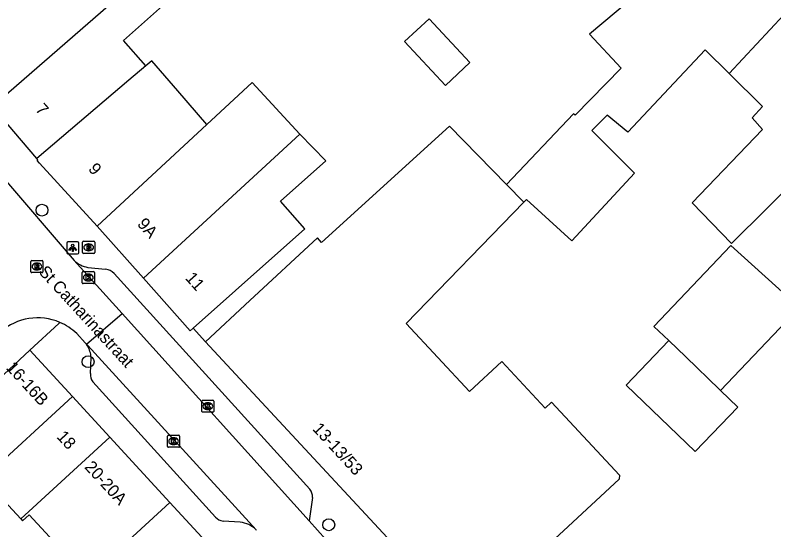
# Model space of a CAD drawing. Extents: x 160664 to 161506, y 382245 to 383288.
# Drawn here: x 160852.6 to 160915.2, y 383074 to 383116.5 of the extents above; entities that cross this region are included whole.
import ezdxf

# ---------------------------------------------------------------- set-up
doc = ezdxf.new("R2010")
doc.units = 0
for name, color, linetype in [('IMGEO_Boom', 7, 'Continuous'), ('IMGEO_Brandkraan', 7, 'Continuous'), ('IMGEO_Kolk', 7, 'Continuous'), ('IMGEO_Lichtpunt', 7, 'Continuous'), ('IMGEO_Openbare_ruimte_label', 7, 'Continuous'), ('IMGEO_Pand', 7, 'Continuous'), ('IMGEO_Pand_nummerreeks', 7, 'Continuous'), ('IMGEO_Rijbaan_lokaal_open', 7, 'Continuous'), ('IMGEO_Rioolput', 7, 'Continuous'), ('IMGEO_Voetpad_open', 7, 'Continuous')]:
    doc.layers.add(name, color=color, linetype=linetype)

msp = doc.modelspace()

# ---------------------------------------------------------------- linework, layer by layer
at = {"layer": 'IMGEO_Boom'}
for centre in [(160854.782, 383100.356), (160858.596, 383087.847), (160878.479, 383074.385)]:
    msp.add_circle(centre, 0.489, dxfattribs=at)
at = {"layer": 'IMGEO_Brandkraan'}
for p, q in [((160858.142, 383096.859), (160858.142, 383097.711)), ((160858.217, 383097.785), (160859.069, 383097.785)), ((160859.143, 383097.711), (160859.143, 383096.859)), ((160858.63, 383097.565), (160858.655, 383097.565)), ((160859.069, 383096.785), (160858.217, 383096.785)), ((160858.653, 383097.005), (160858.628, 383097.005))]:
    msp.add_line(p, q, dxfattribs=at)
for points in [[(160858.142, 383096.859), (160858.142, 383097.711)], [(160858.217, 383097.785), (160859.069, 383097.785)], [(160859.143, 383097.711), (160859.143, 383096.859)], [(160858.49, 383097.485), (160858.49, 383097.085), (160858.703, 383097.085)], [(160858.721, 383097.485), (160858.49, 383097.485)], [(160858.669, 383097.404), (160858.615, 383097.404), (160858.615, 383097.328)], [(160858.615, 383097.328), (160858.668, 383097.328)], [(160858.677, 383097.252), (160858.615, 383097.252), (160858.615, 383097.171)], [(160858.615, 383097.171), (160858.677, 383097.171)], [(160859.069, 383096.785), (160858.217, 383096.785)]]:
    msp.add_lwpolyline(points, dxfattribs=at)
for centre, radius, start, end in [((160858.219, 383097.709), 0.0765, 91.55205, 178.44795), ((160858.219, 383097.709), 0.0765, 91.55205, 178.44795), ((160859.067, 383097.709), 0.0765, 1.55205, 88.44795), ((160859.067, 383097.709), 0.0765, 1.55205, 88.44795), ((160858.67, 383097.366), 0.0379, 267.82845, 90.93552), ((160858.678, 383097.211), 0.0404, 269.87594, 90.50774), ((160858.709, 383097.336), 0.251, 268.66757, 293.53466), ((160858.725, 383097.34), 0.145, 59.4692, 91.53667), ((160858.75, 383097.387), 0.0922, 285.51372, 58.15012), ((160858.755, 383097.195), 0.105, 301.31148, 78.98903), ((160858.219, 383096.861), 0.0765, 181.55205, 268.44795), ((160858.219, 383096.861), 0.0765, 181.55205, 268.44795), ((160859.067, 383096.861), 0.0765, 271.55205, 358.44795), ((160859.067, 383096.861), 0.0765, 271.55205, 358.44795)]:
    msp.add_arc(centre, radius, start, end, dxfattribs=at)
for centre, major_axis, ratio, start_param, end_param in [((160858.629, 383097.285), (-0.387, 0.002), 0.722429, 4.712389, 7.853982), ((160858.654, 383097.285), (-0.39, 0.002), 0.717154, 1.570796, 4.712389)]:
    msp.add_ellipse(centre, major_axis=major_axis, ratio=ratio, start_param=start_param, end_param=end_param, dxfattribs=at)
at = {"layer": 'IMGEO_Kolk'}
for p, q in [((160858.116, 383094.368), (160858.116, 383095.22)), ((160858.191, 383095.294), (160859.043, 383095.294)), ((160859.117, 383095.22), (160859.117, 383094.368)), ((160858.604, 383095.074), (160858.629, 383095.074)), ((160859.043, 383094.294), (160858.191, 383094.294)), ((160858.627, 383094.514), (160858.602, 383094.514)), ((160867.986, 383083.748), (160867.986, 383084.6)), ((160868.061, 383084.674), (160868.913, 383084.674)), ((160868.987, 383084.6), (160868.987, 383083.748)), ((160868.474, 383084.454), (160868.499, 383084.454)), ((160868.913, 383083.674), (160868.061, 383083.674)), ((160868.497, 383083.894), (160868.472, 383083.894)), ((160865.156, 383080.856), (160865.156, 383081.708)), ((160865.231, 383081.782), (160866.083, 383081.782)), ((160865.644, 383081.562), (160865.669, 383081.562)), ((160866.157, 383081.708), (160866.157, 383080.856)), ((160866.083, 383080.782), (160865.231, 383080.782)), ((160865.667, 383081.002), (160865.642, 383081.002))]:
    msp.add_line(p, q, dxfattribs=at)
for points in [[(160858.116, 383094.368), (160858.116, 383095.22)], [(160858.191, 383095.294), (160859.043, 383095.294)], [(160859.117, 383095.22), (160859.117, 383094.368)], [(160858.437, 383094.994), (160858.56, 383094.994), (160858.56, 383094.843), (160858.69, 383094.994), (160858.854, 383094.994), (160858.708, 383094.843), (160858.861, 383094.594), (160858.709, 383094.594), (160858.624, 383094.758), (160858.56, 383094.691), (160858.56, 383094.594), (160858.437, 383094.594), (160858.437, 383094.994)], [(160859.043, 383094.294), (160858.191, 383094.294)], [(160867.986, 383083.748), (160867.986, 383084.6)], [(160868.061, 383084.674), (160868.913, 383084.674)], [(160868.987, 383084.6), (160868.987, 383083.748)], [(160868.307, 383084.374), (160868.43, 383084.374), (160868.43, 383084.223), (160868.56, 383084.374), (160868.724, 383084.374), (160868.578, 383084.223), (160868.731, 383083.974), (160868.579, 383083.974), (160868.494, 383084.138), (160868.43, 383084.071), (160868.43, 383083.974), (160868.307, 383083.974), (160868.307, 383084.374)], [(160868.913, 383083.674), (160868.061, 383083.674)], [(160865.156, 383080.856), (160865.156, 383081.708)], [(160865.231, 383081.782), (160866.083, 383081.782)], [(160865.477, 383081.482), (160865.6, 383081.482), (160865.6, 383081.331), (160865.73, 383081.482), (160865.894, 383081.482), (160865.748, 383081.331), (160865.901, 383081.082), (160865.749, 383081.082), (160865.664, 383081.246), (160865.6, 383081.179), (160865.6, 383081.082), (160865.477, 383081.082), (160865.477, 383081.482)], [(160866.157, 383081.708), (160866.157, 383080.856)], [(160866.083, 383080.782), (160865.231, 383080.782)]]:
    msp.add_lwpolyline(points, dxfattribs=at)
for centre, start, end in [((160858.193, 383095.218), 91.55205, 178.44795), ((160858.193, 383095.218), 91.55205, 178.44795), ((160859.041, 383095.218), 1.55205, 88.44795), ((160859.041, 383095.218), 1.55205, 88.44795), ((160858.193, 383094.37), 181.55205, 268.44795), ((160858.193, 383094.37), 181.55205, 268.44795), ((160859.041, 383094.37), 271.55205, 358.44795), ((160859.041, 383094.37), 271.55205, 358.44795), ((160868.063, 383084.598), 91.55205, 178.44795), ((160868.063, 383084.598), 91.55205, 178.44795), ((160868.911, 383084.598), 1.55205, 88.44795), ((160868.911, 383084.598), 1.55205, 88.44795), ((160868.063, 383083.75), 181.55205, 268.44795), ((160868.063, 383083.75), 181.55205, 268.44795), ((160868.911, 383083.75), 271.55205, 358.44795), ((160868.911, 383083.75), 271.55205, 358.44795), ((160865.233, 383081.706), 91.55205, 178.44795), ((160865.233, 383081.706), 91.55205, 178.44795), ((160866.081, 383081.706), 1.55205, 88.44795), ((160866.081, 383081.706), 1.55205, 88.44795), ((160865.233, 383080.858), 181.55205, 268.44795), ((160865.233, 383080.858), 181.55205, 268.44795), ((160866.081, 383080.858), 271.55205, 358.44795), ((160866.081, 383080.858), 271.55205, 358.44795)]:
    msp.add_arc(centre, 0.0765, start, end, dxfattribs=at)
for centre, major_axis, ratio, start_param, end_param in [((160858.603, 383094.794), (-0.387, 0.002), 0.722429, 4.712389, 7.853982), ((160858.628, 383094.794), (-0.39, 0.002), 0.717154, 1.570796, 4.712389), ((160868.473, 383084.174), (-0.387, 0.002), 0.722429, 4.712389, 7.853982), ((160868.498, 383084.174), (-0.39, 0.002), 0.717154, 1.570796, 4.712389), ((160865.643, 383081.282), (-0.387, 0.002), 0.722429, 4.712389, 7.853982), ((160865.668, 383081.282), (-0.39, 0.002), 0.717154, 1.570796, 4.712389)]:
    msp.add_ellipse(centre, major_axis=major_axis, ratio=ratio, start_param=start_param, end_param=end_param, dxfattribs=at)
at = {"layer": 'IMGEO_Lichtpunt'}
for p, q in [((160857.731, 383097.737), (160856.923, 383097.737)), ((160857.731, 383097.737), (160856.923, 383097.737)), ((160856.829, 383097.642), (160856.829, 383096.835)), ((160856.829, 383097.642), (160856.829, 383096.835)), ((160857.825, 383096.835), (160857.825, 383097.642)), ((160857.825, 383096.835), (160857.825, 383097.642)), ((160856.923, 383096.741), (160857.731, 383096.741)), ((160856.923, 383096.741), (160857.731, 383096.741))]:
    msp.add_line(p, q, dxfattribs=at)
for points in [[(160857.203, 383097.306), (160857.242, 383097.278), (160857.054, 383097.016), (160857.016, 383097.043), (160857.203, 383097.306)], [(160857.305, 383097.258), (160857.352, 383097.258), (160857.352, 383096.936), (160857.305, 383096.936), (160857.305, 383097.258)], [(160857.415, 383097.278), (160857.453, 383097.305), (160857.64, 383097.043), (160857.601, 383097.015), (160857.415, 383097.278)]]:
    msp.add_lwpolyline(points, dxfattribs=at)
msp.add_circle((160857.328, 383097.44), 0.0994, dxfattribs=at)
for centre, start, end in [((160856.923, 383097.642), 90, 180), ((160856.923, 383097.642), 90, 180), ((160857.731, 383097.642), 0, 90), ((160857.731, 383097.642), 0, 90), ((160856.923, 383096.835), 180, 270), ((160856.923, 383096.835), 180, 270), ((160857.731, 383096.835), 270, 0), ((160857.731, 383096.835), 270, 360)]:
    msp.add_arc(centre, 0.0946, start, end, dxfattribs=at)
at = {"layer": 'IMGEO_Pand'}
for points in [[(160901.674, 383121.447), (160904.415, 383118.611), (160900.01, 383114.885), (160902.622, 383112.091), (160898.826, 383108.199), (160898.705, 383108.319), (160893.163, 383102.485)], [(160911.568, 383111.629), (160919.466, 383120.156)], [(160862.78, 383119.438), (160850.763, 383108.963)], [(160863.37, 383112.275), (160861.516, 383114.358), (160864.744, 383117.232), (160863.018, 383119.171), (160862.78, 383119.438)], [(160886.764, 383116.165), (160884.732, 383114.27), (160888.111, 383110.647), (160890.144, 383112.543), (160886.764, 383116.165)], [(160924.955, 383115.295), (160918.533, 383108.569), (160919.047, 383108.055), (160916.572, 383105.4), (160918.208, 383104.015), (160914.661, 383100.492), (160911.75, 383097.6), (160908.493, 383100.969), (160914.309, 383107.011), (160913.458, 383107.969), (160914.317, 383108.92), (160911.568, 383111.629)], [(160911.568, 383111.629), (160909.574, 383113.593), (160903.171, 383106.798), (160901.476, 383108.194), (160900.204, 383106.927), (160903.729, 383103.405), (160898.547, 383097.837), (160894.821, 383101.251), (160894.598, 383101.021)], [(160863.37, 383112.275), (160861.967, 383111.081), (160854.374, 383104.619)], [(160868.41, 383107.426), (160865.997, 383110.223), (160863.864, 383112.695), (160863.37, 383112.275)], [(160876.09, 383106.619), (160872.156, 383110.887), (160868.41, 383107.426)], [(160854.374, 383104.619), (160850.691, 383108.893), (160850.763, 383108.963)], [(160859.34, 383099.047), (160868.41, 383107.426)], [(160893.163, 383102.485), (160888.456, 383107.291), (160877.881, 383097.692), (160877.537, 383098.061), (160871.966, 383092.888), (160868.302, 383089.485)], [(160876.09, 383106.619), (160863.167, 383094.748)], [(160867.29, 383090.619), (160870.776, 383093.722), (160876.511, 383098.827), (160874.481, 383101.107), (160878.226, 383104.441), (160876.09, 383106.619)], [(160859.34, 383099.047), (160854.573, 383104.237), (160854.382, 383104.456), (160854.457, 383104.522), (160854.374, 383104.619)], [(160894.598, 383101.021), (160893.163, 383102.485)], [(160894.598, 383101.021), (160884.874, 383091.014), (160890.11, 383085.375), (160892.788, 383087.862), (160896.364, 383084.012), (160896.889, 383084.499), (160902.487, 383078.472), (160902.474, 383078.136), (160897.856, 383073.872), (160889.751, 383066.388)], [(160863.167, 383094.748), (160859.34, 383099.047)], [(160910.853, 383085.463), (160917.378, 383092.31), (160911.703, 383097.446), (160905.334, 383090.764), (160906.562, 383089.584)], [(160867.29, 383090.619), (160867.041, 383090.397), (160863.167, 383094.748)], [(160910.853, 383085.463), (160912.276, 383084.096), (160908.754, 383080.429), (160903.039, 383085.916), (160906.562, 383089.584)], [(160906.562, 383089.584), (160907.966, 383088.236), (160910.766, 383085.546), (160910.853, 383085.463)], [(160889.751, 383066.388), (160868.302, 383089.485)], [(160846.509, 383082.026), (160853.777, 383088.801)], [(160857.306, 383084.969), (160853.777, 383088.801)], [(160849.978, 383078.246), (160857.306, 383084.969)], [(160857.306, 383084.969), (160860.397, 383081.613)], [(160860.397, 383081.613), (160853.04, 383074.862)], [(160860.397, 383081.613), (160865.361, 383076.222)], [(160845.322, 383074.18), (160847.166, 383072.195), (160851.673, 383076.352), (160853.04, 383074.862)], [(160865.361, 383076.222), (160854.791, 383066.524)], [(160865.361, 383076.222), (160869.643, 383071.573)], [(160853.04, 383074.862), (160853.185, 383074.704), (160853.735, 383075.209), (160856.097, 383072.635), (160848.217, 383064.883), (160850.226, 383062.693), (160853.621, 383065.808), (160853.799, 383065.614), (160854.791, 383066.524)]]:
    msp.add_lwpolyline(points, dxfattribs=at)
at = {"layer": 'IMGEO_Rijbaan_lokaal_open'}
for points in [[(160851.37, 383103.314), (160857.45, 383096.213)], [(160861.408, 383091.826), (160857.45, 383096.213)], [(160858.461, 383089.297), (160861.408, 383091.826)], [(160876.857, 383074.703), (160861.408, 383091.826)], [(160858.461, 383089.297), (160858.35, 383089.418), (160857.654, 383090.17)], [(160858.461, 383089.297), (160858.568, 383089.18), (160872.472, 383073.976)], [(160876.857, 383074.703), (160878.231, 383073.18)], [(160872.52, 383073.923), (160872.472, 383073.976)]]:
    msp.add_lwpolyline(points, dxfattribs=at)
for centre, radius, start, end in [((160854.434, 383086.816), 4.65, 66.85453, 131.08711), ((160854.419, 383086.797), 4.674, 46.19169, 66.77081)]:
    msp.add_arc(centre, radius, start, end, dxfattribs=at)
at = {"layer": 'IMGEO_Rioolput'}
for p, q in [((160853.868, 383095.274), (160853.868, 383096.126)), ((160853.943, 383096.2), (160854.795, 383096.2)), ((160854.356, 383095.98), (160854.381, 383095.98)), ((160854.869, 383096.126), (160854.869, 383095.274)), ((160854.795, 383095.2), (160853.943, 383095.2)), ((160854.379, 383095.42), (160854.354, 383095.42))]:
    msp.add_line(p, q, dxfattribs=at)
for points in [[(160853.868, 383095.274), (160853.868, 383096.126)], [(160853.943, 383096.2), (160854.795, 383096.2)], [(160854.457, 383095.898), (160854.205, 383095.9), (160854.205, 383095.5)], [(160854.383, 383095.819), (160854.329, 383095.819), (160854.329, 383095.738)], [(160854.869, 383096.126), (160854.869, 383095.274)], [(160854.795, 383095.2), (160853.943, 383095.2)], [(160854.205, 383095.5), (160854.329, 383095.5), (160854.329, 383095.662), (160854.34, 383095.662)], [(160854.329, 383095.738), (160854.381, 383095.738)], [(160854.387, 383095.633), (160854.458, 383095.5), (160854.598, 383095.5), (160854.533, 383095.626)]]:
    msp.add_lwpolyline(points, dxfattribs=at)
for centre, radius, start, end in [((160853.945, 383096.124), 0.0765, 91.55205, 178.44795), ((160853.945, 383096.124), 0.0765, 91.55205, 178.44795), ((160854.389, 383095.723), 0.0964, 77.00612, 93.18647), ((160854.403, 383095.78), 0.0378, 276.66336, 79.67722), ((160854.456, 383095.788), 0.109, 350.36119, 89.41601), ((160854.793, 383096.124), 0.0765, 1.55205, 88.44795), ((160854.793, 383096.124), 0.0765, 1.55205, 88.44795), ((160853.945, 383095.276), 0.0765, 181.55205, 268.44795), ((160853.945, 383095.276), 0.0765, 181.55205, 268.44795), ((160854.339, 383095.609), 0.0533, 26.02933, 88.69889), ((160854.365, 383095.927), 0.19, 274.7715, 282.96867), ((160854.454, 383095.788), 0.112, 277.58423, 350.98172), ((160854.438, 383095.573), 0.108, 29.51342, 73.79051), ((160854.793, 383095.276), 0.0765, 271.55205, 358.44795), ((160854.793, 383095.276), 0.0765, 271.55205, 358.44795)]:
    msp.add_arc(centre, radius, start, end, dxfattribs=at)
for centre, major_axis, ratio, start_param, end_param in [((160854.355, 383095.7), (-0.387, 0.002), 0.722429, 4.712389, 7.853982), ((160854.38, 383095.7), (-0.39, 0.002), 0.717154, 1.570796, 4.712389)]:
    msp.add_ellipse(centre, major_axis=major_axis, ratio=ratio, start_param=start_param, end_param=end_param, dxfattribs=at)
at = {"layer": 'IMGEO_Voetpad_open'}
for points in [[(160858.577, 383095.637), (160860.047, 383095.484)], [(160860.739, 383095.124), (160876.923, 383077.314)], [(160853.777, 383088.801), (160856.172, 383091.007), (160856.262, 383091.092)], [(160868.302, 383089.485), (160867.29, 383090.619)], [(160858.543, 383089.157), (160858.461, 383089.297)], [(160858.785, 383086.865), (160858.839, 383088.207)], [(160869.131, 383075.013), (160858.982, 383086.186)], [(160877.141, 383076.644), (160876.857, 383074.703)], [(160871.161, 383074.601), (160869.748, 383074.688)]]:
    msp.add_lwpolyline(points, dxfattribs=at)
for centre, radius, start, end in [((160858.863, 383097.586), 1.97, 224.19427, 261.66336), ((160859.889, 383094.336), 1.159, 42.8441, 82.18618), ((160856.85, 383088.108), 1.992, 2.83891, 31.77296), ((160859.814, 383086.796), 1.031, 176.13686, 216.22147), ((160876.115, 383076.681), 1.026, 357.95131, 38.09568), ((160869.866, 383075.66), 0.979, 221.35994, 263.08471), ((160870.864, 383072.292), 2.328, 46.33901, 82.68342)]:
    msp.add_arc(centre, radius, start, end, dxfattribs=at)

# ---------------------------------------------------------------- texts
at = {"layer": 'IMGEO_Openbare_ruimte_label'}
msp.add_text('St Catharinastraat', height=1, rotation=312.52804, dxfattribs=at).set_placement((160854.451, 383095.226))
at = {"layer": 'IMGEO_Pand_nummerreeks'}
for s, rotation, p in [('7', 311.67674, (160854.186, 383108.628)), ('9', 311.67674, (160858.558, 383103.717)), ('9A', 311.67674, (160862.601, 383099.174)), ('11', 311.67692, (160866.573, 383094.712)), ('16-16B', 312.64504, (160851.762, 383087.299)), ('13-13/53', 312.68515, (160877.078, 383082.259)), ('18', 312.64504, (160855.943, 383081.608)), ('20-20A', 312.63931, (160858.245, 383079.108))]:
    msp.add_text(s, height=1, rotation=rotation, dxfattribs=at).set_placement(p)

doc.saveas('drawing.dxf')
